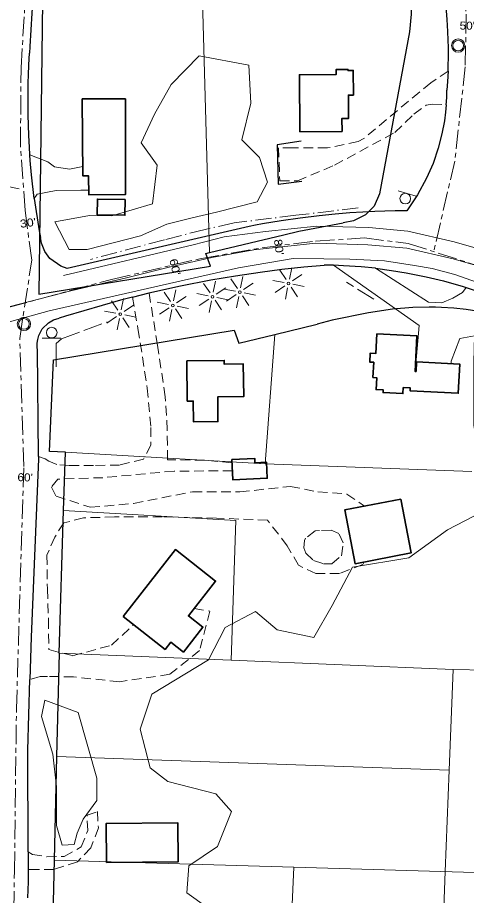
# Model space of a CAD drawing. Extents: x -861682 to -858969, y -1797841 to -1795153.
# Drawn here: x -860350 to -860013, y -1796801 to -1796143 of the extents above; entities that cross this region are included whole.
import ezdxf

# ---------------------------------------------------------------- set-up
doc = ezdxf.new("R2010")
doc.units = 0
doc.header["$LTSCALE"] = 2.4
for name, pattern in [('DOT_DASHED', [7.7, 5, -1.2, 0.3, -1.2]), ('LONG_DASH_SHORT_DASH', [9.9, 6, -1.2, 1.5, -1.2]), ('LONG_DASHED', [7.5, 6, -1.5]), ('MEDIUM_DASHED', [4.5, 3, -1.5])]:
    doc.linetypes.add(name, pattern=pattern)
for name, color, linetype, lineweight in [('10', 7, 'Continuous', 25), ('11', 7, 'Continuous', 13), ('12', 7, 'Continuous', 35), ('14', 7, 'Continuous', 25), ('17', 7, 'Continuous', 13), ('18', 7, 'Continuous', 13), ('21', 7, 'Continuous', 13), ('30', 7, 'Continuous', 13), ('32', 7, 'LONG_DASH_SHORT_DASH', 13), ('36', 7, 'Continuous', 13), ('42', 7, 'Continuous', 25), ('52', 7, 'LONG_DASHED', 13), ('54', 7, 'Continuous', 13), ('63', 7, 'DOT_DASHED', 13)]:
    doc.layers.add(name, color=color, linetype=linetype, lineweight=lineweight)
doc.layers.add('43', color=7, linetype='Continuous')

msp = doc.modelspace()

# ---------------------------------------------------------------- linework, layer by layer
at = {"layer": '10'}
for p, q in [((-860263.638, -1796352.617), (-860251.179, -1796349.506)), ((-860013.263, -1796345.31), (-859998.682, -1796350.09)), ((-860334.259, -1796472.123), (-860334.812, -1796392.058)), ((-860341.985, -1796768.533), (-860341.964, -1796781.747))]:
    msp.add_line(p, q, dxfattribs=at)
for points in [[(-860026.826, -1796183.149), (-860026.784, -1796182.074), (-860026.672, -1796178.744), (-860026.561, -1796173.235), (-860026.542, -1796171.031), (-860026.537, -1796168.827), (-860026.558, -1796165.521), (-860026.666, -1796160.012), (-860026.915, -1796153.405), (-860027.452, -1796144.606), (-860028.334, -1796134.728), (-860029.51, -1796124.88), (-860031.161, -1796113.985), (-860033.615, -1796100.991), (-860036.318, -1796089.175), (-860040.692, -1796073.236), (-860046.644, -1796055.336), (-860048.39, -1796050.652)], [(-860335.676, -1796089.767), (-860337.997, -1796121.135), (-860339.19, -1796139.831), (-860340.577, -1796164.709), (-860340.829, -1796169.703)], [(-860340.607, -1796245.897), (-860341.003, -1796240.184), (-860341.465, -1796231.38), (-860341.757, -1796223.672), (-860341.942, -1796215.96), (-860342, -1796211.552), (-860342.024, -1796207.144), (-860342.024, -1796206.042), (-860342.013, -1796202.736), (-860341.967, -1796198.329), (-860341.834, -1796191.718), (-860341.664, -1796186.211), (-860341.335, -1796178.504), (-860340.829, -1796169.703)], [(-860026.826, -1796183.149), (-860027.237, -1796190.852), (-860027.732, -1796197.446)], [(-860028.208, -1796208.38), (-860028.021, -1796206.218), (-860027.835, -1796202.444), (-860027.732, -1796197.446)], [(-860028.208, -1796208.38), (-860028.687, -1796213.902), (-860029.565, -1796220.455), (-860031.406, -1796230.199), (-860034.182, -1796240.861), (-860038.108, -1796252.327), (-860042.924, -1796263.448), (-860049.721, -1796276.053), (-860057.66, -1796287.972)], [(-860337.358, -1796278.574), (-860339.351, -1796261.055), (-860340.318, -1796250.078), (-860340.607, -1796245.897)], [(-860337.358, -1796278.574), (-860333.651, -1796302.942), (-860332.769, -1796307.864)], [(-860057.66, -1796287.972), (-860060.965, -1796287.986), (-860066.475, -1796288.05), (-860074.187, -1796288.222), (-860081.896, -1796288.489), (-860090.702, -1796288.913), (-860100.6, -1796289.54), (-860111.585, -1796290.422), (-860123.647, -1796291.618), (-860137.87, -1796293.335), (-860152.049, -1796295.382), (-860166.176, -1796297.756), (-860171.268, -1796298.694), (-860176.178, -1796299.641), (-860312.717, -1796331.081)], [(-860312.717, -1796331.081), (-860317.426, -1796329.42), (-860325.553, -1796323.6), (-860329.474, -1796318.297), (-860331.972, -1796312.194), (-860332.769, -1796307.864)], [(-860251.179, -1796349.506), (-860249.106, -1796348.989), (-860227.59, -1796344.215), (-860204.877, -1796339.785), (-860186.409, -1796336.639), (-860167.878, -1796333.888), (-860151.482, -1796331.79), (-860135.05, -1796330.001), (-860119.685, -1796328.612)], [(-860112.709, -1796328.772), (-860114.685, -1796328.7), (-860119.685, -1796328.612)], [(-860081.181, -1796331.023), (-860092.146, -1796329.93), (-860105.34, -1796329.045), (-860112.709, -1796328.772)], [(-860081.181, -1796331.023), (-860069.162, -1796332.596), (-860058.285, -1796334.363), (-860043.154, -1796337.371), (-860030.293, -1796340.443), (-860015.436, -1796344.598), (-860013.263, -1796345.31)], [(-860263.638, -1796352.617), (-860272.627, -1796354.862), (-860313.849, -1796366.851), (-860318.611, -1796368.377)], [(-860334.812, -1796392.058), (-860335.047, -1796390.381), (-860335.143, -1796388.181), (-860335.101, -1796387.079), (-860334.772, -1796384.517), (-860333.883, -1796381.336), (-860331.304, -1796376.486), (-860326.646, -1796371.834), (-860322.816, -1796369.67), (-860318.611, -1796368.377)], [(-860334.259, -1796472.123), (-860334.248, -1796473.768), (-860339.616, -1796607.458), (-860340.552, -1796639.285)], [(-860341.985, -1796768.533), (-860342.11, -1796692.249), (-860340.552, -1796639.285)], [(-860341.964, -1796781.747), (-860341.95, -1796790.964), (-860342.31, -1796802.996)]]:
    msp.add_lwpolyline(points, dxfattribs=at)
at = {"layer": '11', "linetype": 'MEDIUM_DASHED'}
for points in [[(-860026.826, -1796183.149), (-860039.832, -1796191.881), (-860090.034, -1796233.672), (-860094.268, -1796235.836), (-860117.382, -1796240.764), (-860143.611, -1796240.757), (-860154.009, -1796240.611), (-860153.084, -1796265.414), (-860139.85, -1796265.535), (-860112.07, -1796253.713), (-860066.68, -1796229.214), (-860052.623, -1796215.386), (-860043.23, -1796208.688), (-860038.746, -1796207.94), (-860028.208, -1796208.38)], [(-860188.882, -1796476.786), (-860209.549, -1796474.922), (-860237.418, -1796474.561), (-860237.508, -1796452.126), (-860239.024, -1796427.335), (-860244.847, -1796388.628), (-860251.179, -1796349.506)], [(-860263.638, -1796352.617), (-860259.539, -1796376.17), (-860252.512, -1796420.777), (-860249.796, -1796450.286), (-860249.979, -1796463.512), (-860255.368, -1796474.161), (-860273.299, -1796478.484), (-860292.899, -1796478.798), (-860311.084, -1796478.871), (-860320.297, -1796478.2), (-860326.447, -1796475.627), (-860329.052, -1796473.748), (-860334.259, -1796472.123)], [(-860188.577, -1796482.867), (-860232.425, -1796483.043), (-860285.778, -1796487.98), (-860319.545, -1796489.06), (-860324.479, -1796495.22), (-860320.911, -1796501.819), (-860295.371, -1796510.218), (-860262.793, -1796507.254), (-860218.665, -1796498.575), (-860183.004, -1796498.668), (-860145.235, -1796494.502), (-860124.436, -1796498.67), (-860102.702, -1796500.236), (-860089.569, -1796509.294)], [(-860089.892, -1796551.185), (-860090.682, -1796553.088), (-860108.284, -1796559.788), (-860125.966, -1796559.788), (-860139.077, -1796553.654), (-860147.497, -1796538.979), (-860162.373, -1796519.84), (-860200.637, -1796518.34), (-860241.262, -1796517.322), (-860277.158, -1796517.466), (-860300.299, -1796518.031), (-860315.162, -1796521.869), (-860321.968, -1796532.524), (-860327.818, -1796546.009), (-860327.48, -1796571.513), (-860326.681, -1796594.181), (-860326.354, -1796616.852), (-860308.623, -1796621.504), (-860279.37, -1796613.593), (-860262.921, -1796598.155)], [(-860217.363, -1796586.108), (-860205.554, -1796588.028), (-860213.229, -1796617.579), (-860235.593, -1796635.381), (-860273.357, -1796640.964), (-860307.851, -1796637.324), (-860327.454, -1796636.93), (-860332.886, -1796636.952), (-860340.552, -1796639.285)], [(-860341.985, -1796768.533), (-860338.726, -1796770.405), (-860327.855, -1796772.251), (-860314.868, -1796771.963), (-860302.143, -1796764.827), (-860297.233, -1796752.527), (-860297.752, -1796740.957), (-860289.969, -1796738.328), (-860289.211, -1796750.605), (-860294.82, -1796765.506), (-860304.933, -1796775.938), (-860322.622, -1796781.676), (-860334.194, -1796781.723), (-860341.964, -1796781.747)]]:
    msp.add_lwpolyline(points, dxfattribs=at)
at = {"layer": '11'}
for points in [[(-860300.862, -1796254.611), (-860310.769, -1796256.632), (-860322.127, -1796254.841), (-860327.121, -1796251.104), (-860340.607, -1796245.897)], [(-860296.454, -1796272.338), (-860302.361, -1796272.39), (-860320.788, -1796272.788), (-860335.178, -1796275.513), (-860337.358, -1796278.574)], [(-860051.609, -1796408.327), (-860048.417, -1796373.905), (-860112.709, -1796328.772)], [(-860081.181, -1796331.023), (-860041.403, -1796356.402), (-860031.483, -1796356.835), (-860023.23, -1796353.495), (-860015.927, -1796349.215), (-860013.263, -1796345.31)], [(-859885.594, -1796539.373), (-859871.84, -1796532.369), (-859864.843, -1796569.183), (-859887.024, -1796573.759), (-859901.474, -1796562.953), (-859910.424, -1796568.893), (-859922.463, -1796570.358), (-859944.799, -1796595.009), (-859953.476, -1796597.318), (-859964.301, -1796595.874), (-859972, -1796589.619), (-859979.698, -1796574.223), (-859986.674, -1796556.541), (-859994.373, -1796531.16), (-860007.497, -1796448.604), (-860007.451, -1796401.371), (-860007.058, -1796381.532), (-860017.913, -1796383.701), (-860024.457, -1796400.731), (-860024.45, -1796402.445)]]:
    msp.add_lwpolyline(points, dxfattribs=at)
at = {"layer": '11', "linetype": 'MEDIUM_DASHED'}
msp.add_lwpolyline([(-860133.741, -1796533.42), (-860134.443, -1796535.076), (-860135.13, -1796540.51), (-860133.46, -1796544.518), (-860127.77, -1796550.164), (-860120.203, -1796552.495), (-860114.063, -1796552.47), (-860106.766, -1796546.537), (-860105.624, -1796536.85), (-860108.722, -1796529.777), (-860114.636, -1796527.439), (-860123.374, -1796527.474), (-860126.442, -1796527.959)], close=True, dxfattribs=at)
at = {"layer": '12'}
for points in [[(-860138.416, -1796186.361), (-860138.046, -1796228.655), (-860106.385, -1796228.378), (-860106.47, -1796218.691), (-860101.508, -1796218.647), (-860101.663, -1796201.163), (-860097.88, -1796201.129), (-860098.046, -1796182.701), (-860101.821, -1796182.735), (-860101.827, -1796182.025), (-860110.806, -1796182.101), (-860110.776, -1796185.647), (-860138.42, -1796185.881)], [(-860301.304, -1796204.091), (-860300.8, -1796261.743), (-860296.547, -1796261.706), (-860296.424, -1796275.882), (-860268.779, -1796275.642), (-860268.974, -1796253.194), (-860268.975, -1796253.194), (-860268.975, -1796204.091)], [(-860290.148, -1796290.95), (-860269.351, -1796291.241), (-860269.186, -1796279.447), (-860289.983, -1796279.156)], [(-860080.273, -1796380.171), (-860050.274, -1796381.704), (-860051.634, -1796408.326), (-860050.888, -1796408.364), (-860050.519, -1796401.118), (-860018.03, -1796402.772), (-860019.145, -1796424.679), (-860055.319, -1796422.838), (-860055.211, -1796420.709), (-860060.495, -1796420.441), (-860060.725, -1796424.977), (-860075.578, -1796424.224), (-860075.475, -1796422.197), (-860080.812, -1796421.926), (-860080.359, -1796413.012), (-860083.244, -1796412.865), (-860082.663, -1796401.455), (-860085.626, -1796401.304), (-860085.282, -1796394.552), (-860081.017, -1796394.769)], [(-860222.835, -1796400.345), (-860222.478, -1796430.572), (-860217.99, -1796430.519), (-860217.806, -1796446.13), (-860199.482, -1796445.914), (-860199.7, -1796427.404), (-860180.206, -1796427.174), (-860180.494, -1796402.754), (-860194.728, -1796402.922), (-860194.762, -1796400.015)], [(-860189.004, -1796474.365), (-860188.234, -1796489.712), (-860162.476, -1796488.42), (-860163.082, -1796476.346), (-860171.749, -1796476.781), (-860171.913, -1796473.506)], [(-860062.296, -1796504.077), (-860054.577, -1796544.43), (-860096.64, -1796552.476), (-860104.359, -1796512.123)], [(-860270.717, -1796592.065), (-860231.479, -1796541.841), (-860201.237, -1796565.468), (-860221.63, -1796591.57), (-860210.811, -1796600.023), (-860225.454, -1796618.765), (-860234.935, -1796611.358), (-860239.137, -1796616.737)], [(-860283.202, -1796776.557), (-860229.359, -1796776.105), (-860229.605, -1796746.817), (-860283.448, -1796747.269)]]:
    msp.add_lwpolyline(points, close=True, dxfattribs=at)
at = {"layer": '14'}
msp.add_lwpolyline([(-860137.082, -1796235.594), (-860155.017, -1796238.35), (-860154.286, -1796267.88), (-860136.496, -1796265.717)], dxfattribs=at)
at = {"layer": '17'}
for p, q in [((-860357.218, -1796269.678), (-860348.738, -1796271.402)), ((-860145.892, -1796339.057), (-860144.166, -1796330.657)), ((-860182.471, -1796345.58), (-860180.745, -1796337.18)), ((-860148.352, -1796339.517), (-860153.142, -1796332.389)), ((-860143.692, -1796340.457), (-860136.596, -1796335.717)), ((-860205.463, -1796349.429), (-860210.253, -1796342.301)), ((-860203.003, -1796348.969), (-860201.277, -1796340.569)), ((-860184.931, -1796346.04), (-860189.721, -1796338.912)), ((-860180.271, -1796346.98), (-860173.175, -1796342.24)), ((-860149.852, -1796341.717), (-860158.314, -1796340.043)), ((-860143.252, -1796342.977), (-860134.772, -1796344.701)), ((-860235.194, -1796355.924), (-860239.984, -1796348.796)), ((-860232.734, -1796355.464), (-860231.008, -1796347.064)), ((-860206.963, -1796351.629), (-860215.425, -1796349.955)), ((-860200.803, -1796350.369), (-860193.707, -1796345.629)), ((-860186.431, -1796348.24), (-860194.893, -1796346.566)), ((-860179.831, -1796349.5), (-860171.351, -1796351.224)), ((-860149.312, -1796344.217), (-860156.538, -1796349.073)), ((-860148.932, -1796354.177), (-860147.252, -1796345.577)), ((-860144.592, -1796345.117), (-860139.792, -1796352.331)), ((-860274.576, -1796362.503), (-860279.366, -1796355.375)), ((-860272.116, -1796362.043), (-860270.39, -1796353.643)), ((-860236.694, -1796358.124), (-860245.156, -1796356.45)), ((-860230.534, -1796356.864), (-860223.438, -1796352.124)), ((-860206.423, -1796354.129), (-860213.649, -1796358.985)), ((-860206.043, -1796364.089), (-860204.363, -1796355.489)), ((-860201.703, -1796355.029), (-860196.903, -1796362.243)), ((-860200.363, -1796352.889), (-860191.883, -1796354.613)), ((-860185.891, -1796350.74), (-860193.117, -1796355.596)), ((-860185.511, -1796360.7), (-860183.831, -1796352.1)), ((-860181.171, -1796351.64), (-860176.371, -1796358.854)), ((-860276.076, -1796364.703), (-860284.538, -1796363.029)), ((-860269.916, -1796363.443), (-860262.82, -1796358.703)), ((-860236.154, -1796360.624), (-860243.38, -1796365.48)), ((-860235.774, -1796370.584), (-860234.094, -1796361.984)), ((-860231.434, -1796361.524), (-860226.634, -1796368.738)), ((-860230.094, -1796359.384), (-860221.614, -1796361.108)), ((-860275.536, -1796367.203), (-860282.762, -1796372.059)), ((-860275.156, -1796377.163), (-860273.476, -1796368.563)), ((-860270.816, -1796368.103), (-860266.016, -1796375.317)), ((-860269.476, -1796365.963), (-860260.996, -1796367.687))]:
    msp.add_line(p, q, dxfattribs=at)
for centre in [(-860146.552, -1796342.417), (-860183.131, -1796348.94), (-860203.663, -1796352.329), (-860233.394, -1796358.824), (-860272.776, -1796365.403)]:
    msp.add_circle(centre, 1, dxfattribs=at)
at = {"layer": '18'}
for points in [[(-860297.718, -1796317.009), (-860311.188, -1796316.89), (-860322.002, -1796296.191), (-860295.814, -1796291.472), (-860279.037, -1796291.562), (-860248.631, -1796282.79), (-860245.105, -1796253.695), (-860257.065, -1796237.022), (-860247.093, -1796215.432), (-860234.528, -1796193.111), (-860213.685, -1796171.662), (-860176.29, -1796178.66), (-860174.858, -1796207.24), (-860181.707, -1796234.71), (-860168.358, -1796248.062), (-860162.29, -1796266.44), (-860170.195, -1796281.159), (-860200.609, -1796288.986), (-860218.767, -1796293.162), (-860237.867, -1796297.819), (-860257.637, -1796306.734)], [(-860320.628, -1796748.842), (-860320.744, -1796719.794), (-860323.441, -1796695.244), (-860331.82, -1796666.938), (-860329.506, -1796654.885), (-860304.437, -1796663.994), (-860290.305, -1796713.296), (-860290.474, -1796730.064), (-860300.573, -1796744.038), (-860305.019, -1796754.447), (-860307.346, -1796762.958), (-860316.319, -1796763.467)]]:
    msp.add_lwpolyline(points, close=True, dxfattribs=at)
msp.add_lwpolyline([(-860207.965, -1796810.021), (-860222.887, -1796799.219), (-860221.315, -1796778.903), (-860199.882, -1796764.411), (-860189.36, -1796738.155), (-860200.985, -1796724.976), (-860237.156, -1796715.675), (-860250.422, -1796705.574), (-860257.859, -1796676.555), (-860249.226, -1796650.307), (-860206.557, -1796624.502), (-860194.165, -1796600.256), (-860171.305, -1796588.357), (-860155.191, -1796601.99), (-860127.537, -1796607.783), (-860113.699, -1796583.875), (-860098.661, -1796554.977), (-860056.32, -1796548.121), (-860027.255, -1796527.086), (-860001.229, -1796513.478)], dxfattribs=at)
at = {"layer": '21'}
for p, q in [((-860064.219, -1796272.943), (-860050.805, -1796276.963)), ((-860317.474, -1796383.297), (-860331.478, -1796383.351))]:
    msp.add_line(p, q, dxfattribs=at)
for centre in [(-860058.922, -1796278.768), (-860324.236, -1796379.264)]:
    msp.add_circle(centre, 4, dxfattribs=at)
at = {"layer": '30'}
for p, q in [((-860164.144, -1796477.6), (-860156.818, -1796380.737)), ((-860313.919, -1796468.886), (-860164.144, -1796477.6)), ((-860164.144, -1796477.6), (-860009.11, -1796483.248)), ((-860318.59, -1796619.665), (-860189.554, -1796624.849)), ((-860022.934, -1796631.684), (-860026.049, -1796707.275)), ((-859659.085, -1796641.503), (-860022.934, -1796631.684)), ((-860320.6, -1796697.121), (-860026.049, -1796707.275)), ((-860322.443, -1796774.784), (-860142.618, -1796779.921)), ((-859702.728, -1796792.888), (-860142.618, -1796779.921))]:
    msp.add_line(p, q, dxfattribs=at)
for points in [[(-860100.109, -1795989.121), (-860213.051, -1796058.32), (-860205.797, -1796319.285)], [(-860315.423, -1796512.651), (-860186.11, -1796520.201), (-860189.554, -1796624.849), (-860022.934, -1796631.684)], [(-860026.049, -1796707.275), (-860029.004, -1796783.27), (-860034.257, -1796926.914)], [(-860142.618, -1796779.921), (-860151.652, -1796981.121), (-860326.603, -1796977.139)]]:
    msp.add_lwpolyline(points, dxfattribs=at)
at = {"layer": '32'}
for points in [[(-860274.26, -1795653.513), (-860250.487, -1795671.004), (-860229.924, -1795692.424), (-860208.503, -1795727.553), (-860157.095, -1795804.667), (-860105.686, -1795892.062), (-860073.984, -1795950.325), (-860046.566, -1796011.159), (-860031.143, -1796049.715), (-860017.434, -1796100.268), (-860013.15, -1796140.538), (-860014.007, -1796179.951), (-860021.718, -1796250.638), (-860037.649, -1796318.494)], [(-860350.575, -1797816.671), (-860352.537, -1797784.701), (-860351.442, -1797711.343), (-860351.99, -1797541.086), (-860353.632, -1797469.37), (-860356.368, -1797360.975), (-860359.105, -1797223.017), (-860359.105, -1797136.52), (-860357.161, -1797049.888), (-860352.185, -1796782.715), (-860350.693, -1796661.317), (-860345.219, -1796479.719), (-860348.204, -1796383.696), (-860339.249, -1796324.987), (-860344.224, -1796287.673), (-860347.707, -1796239.412), (-860347.209, -1796180.704), (-860344.224, -1796130.951), (-860339.746, -1796052.839), (-860328.991, -1795893.364)], [(-861651.105, -1796687.844), (-861333.558, -1796608.31), (-860734.009, -1796456.297), (-860402.78, -1796372.876), (-860279.286, -1796339.345), (-860213.04, -1796323.806), (-860166.423, -1796315.627), (-860126.348, -1796310.72), (-860089.545, -1796308.267), (-860056.831, -1796312.356), (-859995.492, -1796331.984), (-859827.834, -1796395.777), (-859764.042, -1796414.588), (-859688.8, -1796435.852), (-859629.915, -1796444.03), (-859562.034, -1796449.756), (-859471.253, -1796448.938), (-859395.193, -1796443.213), (-859240.62, -1796421.131), (-859002.083, -1796383.657)]]:
    msp.add_lwpolyline(points, dxfattribs=at)
at = {"layer": '36'}
for centre, radius in [((-860019.281, -1796164.055), 5), ((-860019.281, -1796164.055), 4), ((-860345.044, -1796372.735), 5), ((-860345.044, -1796372.735), 4)]:
    msp.add_circle(centre, radius, dxfattribs=at)
at = {"layer": '42'}
for p, q in [((-860205.797, -1796319.285), (-860149.993, -1796305.887)), ((-860156.818, -1796380.737), (-860125.144, -1796372.987)), ((-860315.423, -1796512.651), (-860313.919, -1796468.886)), ((-860318.59, -1796619.665), (-860315.423, -1796512.651)), ((-860318.59, -1796619.665), (-860320.6, -1796697.121)), ((-860320.6, -1796697.121), (-860322.443, -1796774.784)), ((-860322.443, -1796774.784), (-860326.603, -1796977.139))]:
    msp.add_line(p, q, dxfattribs=at)
for points in [[(-860092.863, -1796001.383), (-860088.006, -1796010.415), (-860080.373, -1796026.388), (-860072.135, -1796047.143), (-860066.098, -1796066.137), (-860062.275, -1796081.023), (-860059.18, -1796095.926), (-860057.393, -1796106.542), (-860055.963, -1796117.114), (-860055.293, -1796123.444), (-860055.107, -1796125.554), (-860054.604, -1796134.026), (-860054.556, -1796140.462), (-860055.663, -1796153.755), (-860078.293, -1796275.127)], [(-860331.139, -1796130.629), (-860333.796, -1796350.4), (-860205.004, -1796329.448), (-860208.571, -1796319.923), (-860205.797, -1796319.285)], [(-860078.293, -1796275.127), (-860082.184, -1796284.48), (-860088.729, -1796290.964), (-860097.82, -1796295.386), (-860105.491, -1796296.873)], [(-860149.993, -1796305.887), (-860138.764, -1796303.198), (-860105.491, -1796296.873)], [(-859921.126, -1796388.728), (-859940.748, -1796380.277), (-859963.13, -1796372.557), (-859983.607, -1796367.145), (-860001.905, -1796363.562), (-860013.337, -1796361.916), (-860022.49, -1796360.947), (-860031.708, -1796360.316), (-860036.373, -1796360.145), (-860041.1, -1796360.079), (-860053.275, -1796360.417), (-860068.53, -1796361.752), (-860086.647, -1796364.344), (-860113.909, -1796370.012), (-860125.144, -1796372.987)], [(-860313.919, -1796468.886), (-860325.857, -1796468.313), (-860322.879, -1796399.659), (-860187.369, -1796377.453), (-860183.887, -1796387.125), (-860156.818, -1796380.737)]]:
    msp.add_lwpolyline(points, dxfattribs=at)
at = {"layer": '52'}
msp.add_line((-860082.504, -1796354.204), (-860103.101, -1796341.534), dxfattribs=at)
msp.add_lwpolyline([(-860320.826, -1796404.991), (-860320.861, -1796396.254), (-860320.883, -1796390.822), (-860320.896, -1796387.516), (-860316.896, -1796383.957), (-860282.703, -1796371.304)], dxfattribs=at)
at = {"layer": '54'}
for points in [[(-859545.414, -1796435.904), (-859566.072, -1796433.962), (-859593.018, -1796433.015), (-859601.542, -1796430.963), (-859614.78, -1796430.37), (-859633.232, -1796427.932), (-859658.781, -1796424.611), (-859686.231, -1796420.125), (-859708.957, -1796415.361), (-859745.656, -1796406.939), (-859779.993, -1796398.496), (-859823.842, -1796383.047), (-859893.781, -1796356.484), (-859988.138, -1796320.918), (-860022.25, -1796311.056), (-860057.055, -1796303.09), (-860086.378, -1796300.51), (-860125.376, -1796299.434), (-860163.858, -1796303.314), (-860194.778, -1796307.365), (-860218.117, -1796313.477), (-860315.269, -1796336.538)], [(-860172.631, -1796317.253), (-860204.018, -1796322.811), (-860236.107, -1796330.26), (-860268.193, -1796338.182), (-860308.776, -1796347.556), (-860380.023, -1796366.026), (-860439.712, -1796381.144), (-860499.871, -1796396.736), (-860533.844, -1796405.374), (-860583.86, -1796418.091), (-860653.219, -1796436.08), (-860743.108, -1796458.404), (-860803.739, -1796473.997), (-860915.799, -1796503.257), (-861038.012, -1796533.031), (-861123.178, -1796555.335), (-861206.46, -1796575.979), (-861319.702, -1796605.009), (-861464.557, -1796642.43), (-861630.889, -1796683.009), (-861651.109, -1796688.034)], [(-859979.698, -1796337.212), (-859988.892, -1796333.747), (-860023.004, -1796323.885), (-860057.809, -1796315.919), (-860087.132, -1796313.339), (-860126.13, -1796312.263), (-860172.631, -1796317.253)], [(-860005.566, -1796341.38), (-860021.649, -1796335.54), (-860038.67, -1796331.121), (-860052.141, -1796328.814), (-860074.59, -1796325.361), (-860100.573, -1796324.285), (-860119.94, -1796323.89), (-860143.084, -1796323.747), (-860161.965, -1796326.892), (-860184.149, -1796330.76), (-860326.19, -1796362.976), (-860392.479, -1796381.19)]]:
    msp.add_lwpolyline(points, dxfattribs=at)
at = {"layer": '63'}
msp.add_lwpolyline([(-860094.305, -1796285.693), (-860141.043, -1796291.3), (-860187.308, -1796296.903), (-860209.004, -1796301.819), (-860239.654, -1796309.648), (-860275.487, -1796319.177), (-860295.055, -1796324.31)], dxfattribs=at)

# ---------------------------------------------------------------- texts
at = {"layer": '43'}
for s, rotation, width, p in [("50'", 359.384, 1.1, (-860018.191, -1796152.051)), ("30'", 7.605, 1.15, (-860347.597, -1796300.686)), ("80'", 277.907, 1.15, (-860157.53, -1796309.618)), ("60'", 283.173, 1.2, (-860236.067, -1796324.586)), ("60'", 358.24, 1.1, (-860350.033, -1796490.55))]:
    msp.add_text(s, height=6, rotation=rotation, dxfattribs=dict(at, width=width)).set_placement(p)

doc.saveas('drawing.dxf')
